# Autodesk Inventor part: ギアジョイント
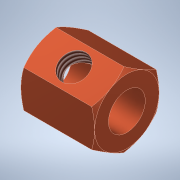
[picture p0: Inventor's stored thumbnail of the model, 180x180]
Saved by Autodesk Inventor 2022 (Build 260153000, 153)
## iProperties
Created: 2024-10
Part Number: ギアジョイント
Material: 銅
Document SubType Name: Modeling
Designer: shimizu
Density: 8.94 g/cm^3
Appearance: 銅 - サテン
Author: shimizu
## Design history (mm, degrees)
sketch "スケッチ1"
  geometry: L1 (-2.021, -3.5)-(-4.041, 0); L2 (-4.041, 0)-(-2.021, 3.5); L3 (-2.021, 3.5)-(2.021, 3.5); L4 (2.021, 3.5)-(4.041, 0); L5 (4.041, 0)-(2.021, -3.5); L6 (2.021, -3.5)-(-2.021, -3.5); L7 (13.951, 0)-(-6.829, 0); C1 r 2 at (0, 0); 2 further points
  constraints: 14 end point, 2 coincident, 1 centre point, 1 horizontal, 1 parallel, 1 point on line, 13 other
  dimensions: "d0" = 7 distance between parallel lines of L1 L4; "d1" = 4 diameter of C1
extrude "押し出し1" new body sketch "スケッチ1" stored distance "d2" = 8; taper "d3" = 0 deg
sketch "スケッチ2"
  geometry: L1 (4, 3.5)-(-4, 3.5) reference; L2 (-4, 3.5)-(-4, 8.5); L3 (-4, 8.5)-(-1.113, 8.5); L4 (-4, 0)-(-4, 3.5) reference; L5 (-1.113, 8.5)-(-4, 3.5); L6 (9.172, 0)-(-12.618, 0); 1 further point
  constraints: 8 end point, 1 horizontal, 1 perpendicular, 1 point on line, 1 vertical
  dimensions: "d4" = 30 deg angle of L2 L5; "d5" = 5 distance of L1.end L2.end
revolve "回転1" sketch "スケッチ2" stored, may be unused: angle "d6" = 90 deg
mirror "ミラー1"
sketch "スケッチ3"
  geometry: C1 r 1.5 at (3.687, 2.021); 1 further point
  constraints: 1 centre point, 1 coincident
  dimensions: "d7" = 3 diameter of C1
extrude "押し出し2" cut sketch "スケッチ3" stored distance "d8" = 0; taper "d9" = 0 deg
feature "ねじ1" dims "d10" = 2.177, "d11" = 0
node "ソリッド1"
